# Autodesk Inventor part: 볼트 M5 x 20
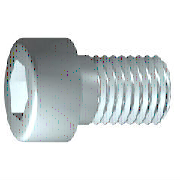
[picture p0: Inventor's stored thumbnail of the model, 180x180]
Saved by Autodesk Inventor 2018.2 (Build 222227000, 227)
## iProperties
Created: 2012-02
Part Number: 볼트 M5 x 20
Material: 스테인리스강
Description: 6각 소켓 머리 캡 나사
Document SubType Name: Modeling
Standard: ISO 4762
Designer: mduedu
Standard Revision: Fourth edition 2004-03-01
Standards Organization: ISO
Language: ko-KR
Size Designation: M5 x 20
Categories: <MemberInstance><Categories><Category DisplayName="조임쇠" InternalName="e4da775c-781d-43d5-af7c-5136215cf5a6" Mnemonic="FSTN"><Category DisplayName="볼트" InternalN
Density: 8.08 g/cm^3
Mass: 5.10181 g
Surface Area: 5.88237 cm^2
Volume: 0.631412 cm^3
Appearance: 반광택
IsCustomPart: 0
Author: mduedu
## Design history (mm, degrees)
sketch "스케치1"
  geometry: L1 (-1.167, 0)-(20, 0); L2 (20, 0)-(20, 2.5); L3 (20, 2.5)-(2, 2.5); L4 (2, 2.5)-(1.509, 2.5); L5 (1.509, 2.5)-(0, 2.5); L6 (0, 2.5)-(0, 4.25); L7 (0, 4.25)-(-5, 4.25); L8 (-5, 4.25)-(-5, 2.309); L9 (-5, 2.309)-(-2.5, 2.309); L10 (-2.5, 2.309)-(-1.167, 0); L11 (-10, 0)-(25, 0) reference; L12 (0, -0.85)-(0, 5.1) reference; L13 (2, 2.5)-(0, 2.5)
  constraints: 22 end point, 6 parallel, 2 collinear, 2 perpendicular, 1 horizontal, 1 point on line
  dimensions: "d1" = 18 distance from line of L3.end L2 (= GEL); "d2" = 0.49086 distance of L4.end L3.end (computed from GAL); "d3" = 5 distance between parallel lines of L8 L6 (= KOH); "d4" = 2.5 distance of L8.end L9.end (= INTI); "d5" = 60 deg angle of L10 L1; "d6" = 5 diameter of L3 L1 (= GD); "d7" = 5 diameter of L5 L1 (= BDM); "d8" = 4.6188 diameter of L9 L1 (= 1.1547 x SW); "d9" = 8.5 diameter of L7 L1 (= KOD); "d26" = 20 distance between parallel lines of L12 L2 (= NLG)
revolve "본체" sketch "스케치1" stored, may be unused: angle "d10" = 90 deg
sketch "스케치2"
  geometry: L1 (0, -5.95)-(0, 5.95) reference; L2 (-5.95, 0)-(5.95, 0) reference; L3 (2.309, 0)-(1.155, -2); L4 (1.155, -2)-(-1.155, -2); L5 (-1.155, -2)-(-2.309, 0); L6 (-2.309, 0)-(-1.155, 2); L7 (-1.155, 2)-(1.155, 2); L8 (1.155, 2)-(2.309, 0); 2 further points
  constraints: 12 end point, 1 coincident, 1 horizontal alignment, 1 point on line, 12 other
extrude "슬롯" join sketch "스케치2" stored distance "d11" = 10; taper "d12" = 0 deg
workplane "Work Plane1"
fillet "Fillet2" dims "d30" = 0.1 (= R)
body "Solid1"
fillet "모깎기1" dims "d17" = 0.5 (= RR)
feature "스레드" dims "d13" = 18 (= GEL), "d14" = 0
chamfer "모따기1" distance "d15" = 0.49076 (= -0.5 x SPD + 0.5 x GD); stored, may be unused: second distance "d16" = 0.49076 (= GUL), angle "d27" = 45 deg
other parameters: "GD" = 5 [user parameter; used in 2 equation terms], "NLG" = 20 [user parameter; used in 1 equation term], "GEL" = 18 [user parameter; used in 2 equation terms], "KOD" = 8.5 [user parameter; used in 1 equation term], "KOH" = 5 [user parameter; used in 1 equation term], "INTI" = 2.5 [user parameter; used in 1 equation term], "GAL" = 0.49076 (= 0.61345 x PTC) [user parameter; used in 1 equation term], "GUL" = 0.49076 (= 0.61345 x PTC) [user parameter; used in 1 equation term], "BDM" = 5 (= NND) [user parameter; used in 1 equation term], "SW" = 4 [user parameter; used in 2 equation terms], "RR" = 0.5 [user parameter; used in 1 equation term], "SPD" = 4.01848 (= NND - 1.2269 x PTC) [user parameter; used in 1 equation term], "d19" = 0, "d28" = 0, "d29" = 0, "R" = 0.1 [user parameter; used in 1 equation term], "TOA" = 30 deg [user parameter], "GD1" = 4.01848 (= THREADDIA - 1.2269 x PTC) [user parameter], "THREADDIA" = 5 [user parameter; used in 1 equation term], "FAWI" = 45 deg [user parameter], "TPU" = 12.5 (computed from PTC) [user parameter], "PTC" = 0.8 [user parameter; used in 5 equation terms], "NND" = 5 [user parameter; used in 2 equation terms], "E0" = 4.62 (= 1.155 x SW) [user parameter]
